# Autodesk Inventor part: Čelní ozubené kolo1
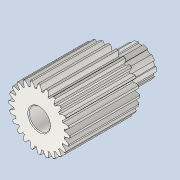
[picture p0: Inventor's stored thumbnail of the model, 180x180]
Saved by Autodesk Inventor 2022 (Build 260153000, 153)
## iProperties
CustomPartVersion: 1
Created: 2025-05
Part Number: Čelní ozubené kolo1
Material: Steel
Document SubType Name: Modeling
Designer: jbart
Categories: <?xml version="1.0" encoding="UTF-16"?> <MemberInstance><Categories><FamilyTemplate><FamilyTemplateParameter ValueType="xs:double" Id="1" ObjectReferenceKey="da
Density: 7.85 g/cm^3
Appearance: Steel
Mass: 20808.8 g
Surface Area: 2605.11 cm^2
Volume: 2650.81 cm^3
Author: jbart
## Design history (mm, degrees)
sketch "Sketch1"
  geometry: C1 r 77.994 at (0, 0)
  constraints: 1 centre point
  dimensions: "d0" = 155.9887 diameter of C1 (= da_da)
extrude "Extrusion1" new body sketch "Sketch1" distance "d1" = 180 (= da_b); taper "d2" = 0 deg
workplane "Work Plane2"
sketch "Sketch2"
  geometry: C1 r 77.994 at (0, 0) reference; C2 r 72 at (0, 0)
  constraints: 1 centre point, 1 coincident
  dimensions: "d3" = 144 diameter of C2 (= da_d)
feature "Roztečný průměr" sketch "Sketch2" dims "d4" = 10, "d5" = 0
workplane "Work Plane8"
workplane "Work Plane9"
feature "Čelní ozubené kolo" dims "da_b" = 180, "da_d" = 144, "da_aw" = 252.61673, "da_da" = 155.9887, "da_df" = 129, "da_dw" = 144.35242, angle "da_beta" = 0 deg, "da_lefttooth" = 0, "da_righttooth" = 0
sketch "Náčrt3"
  geometry: C1 r 34 at (0, 0); 1 further point
  constraints: 1 centre point, 1 coincident
  dimensions: "d49" = 68 diameter of C1
extrude "Vysunutí2" join sketch "Náčrt3" distance "d50" = 10; taper "d51" = 0 deg
sketch "Náčrt4"
  geometry: C1 r 39 at (0, 0); 1 further point
  constraints: 1 centre point, 1 coincident
  dimensions: "d52" = 78 diameter of C1
extrude "Vysunutí3" join sketch "Náčrt4" distance "d53" = 70; taper "d54" = 0 deg
sketch "Náčrt5"
  geometry: L1 (-6, 38.536)-(-6, 35); L2 (-6, 35)-(6, 35); L3 (6, 35)-(6, 38.536); A1 r 39 centre (0, 0) between (-6, 38.536) and (6, 38.536) reference; 2 further points
  constraints: 6 end point, 2 perpendicular, 2 point on circle, 1 midpoint, 1 vertical, 1 vertical alignment
  dimensions: "d55" = 35 distance from line of L2 point (0, 0); "d56" = 12 distance of L1.end L2.end
extrude "Vysunutí4" cut sketch "Náčrt5" stored distance "d57" = 0; taper "d58" = 0 deg
pattern_circular "Kruhové pole1" dims angle "d60" = 360 deg
sketch "Náčrt6"
  geometry: C1 r 27 at (0, 0); 1 further point
  constraints: 1 centre point, 1 coincident
  dimensions: "d62" = 54 diameter of C1
extrude "Vysunutí5" cut sketch "Náčrt6" extent not by distance; stored distance "d63" = 0; taper "d64" = 0 deg
chamfer "Zkosení1" distance "d65" = 2; stored, may be unused: second distance "d66" = 2, angle "d67" = 45 deg
chamfer "Zkosení2" distance "d68" = 1; stored, may be unused: second distance "d69" = 2, angle "d70" = 45 deg
fillet "Zaoblení1" dims "d71" = 3
body "Solid1"
body "Srf1"
node "Promítnutá smyčka1"
other parameters: "d16" = 252.61673 (= da_aw), "d17" = 0, "d34" = 7.5 deg (computed from da_z), "d39" = 0, "d41" = 0, "d43" = 252.61673 (= da_aw), "d46" = 252.61673 (= da_aw), "d47" = 0, "d48" = 0
